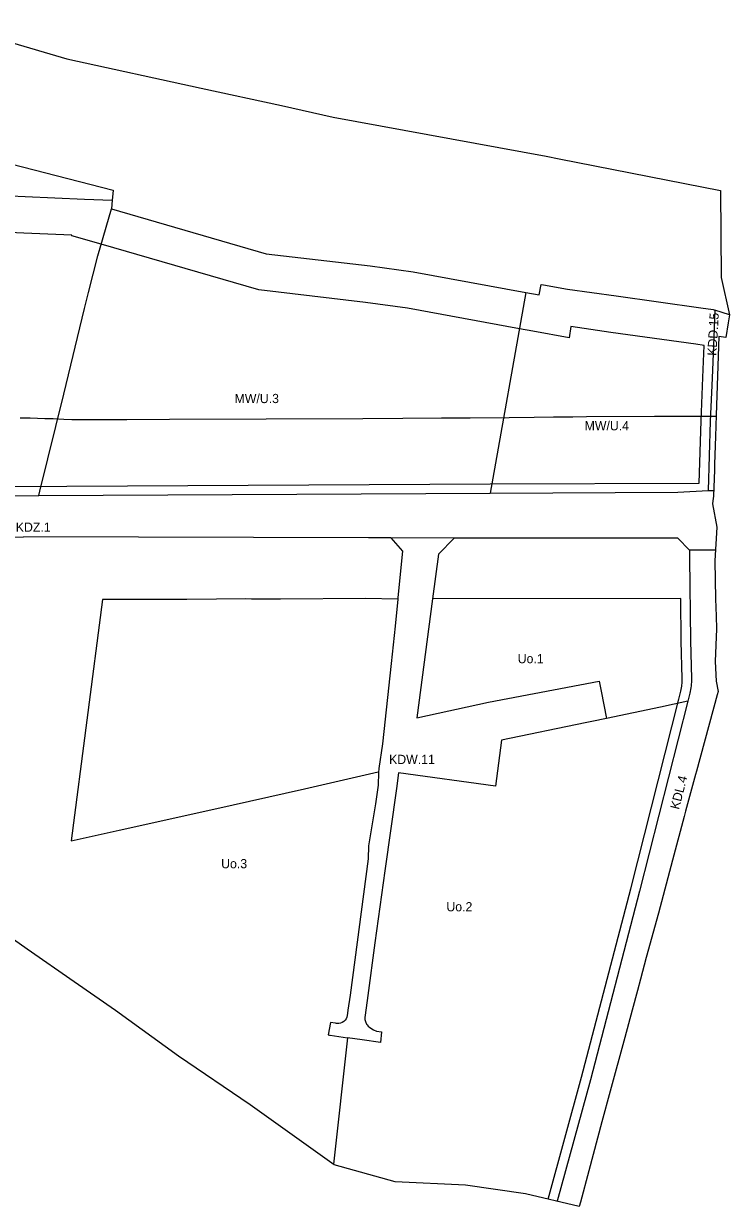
# Model space of a CAD drawing. Extents: x 7416797 to 7419013, y 5549660 to 5551534.
# Drawn here: x 7418629 to 7419013, y 5549660 to 5550303 of the extents above; entities that cross this region are included whole.
import ezdxf

# ---------------------------------------------------------------- set-up
doc = ezdxf.new("R2010")
doc.units = 0
for name, color, linetype in [('LIN_Linia Zabudowy Nieprzekraczalna', 7, 'Continuous'), ('LIN_linie_rozgraniczajace', 7, 'Continuous'), ('LIN_nieprzekraczalna_linia_regulacyjna', 7, 'Continuous'), ('TXT_Oznaczenia_przeznaczen', 7, 'Continuous')]:
    doc.layers.add(name, color=color, linetype=linetype)

msp = doc.modelspace()

# ---------------------------------------------------------------- linework, layer by layer
at = {"layer": 'LIN_Linia Zabudowy Nieprzekraczalna'}
for points in [[(7418999, 5550127.95), (7418994.39, 5550128.59), (7418948.33, 5550135.03), (7418926.58, 5550138.15), (7418925.52, 5550132.14), (7418905.84, 5550135.72), (7418898.57, 5550137.05), (7418837.64, 5550148.14), (7418814.89, 5550151.38), (7418756.87, 5550158.17), (7418671.17, 5550182.99), (7418655.19, 5550187.61), (7418655.21, 5550187.83), (7418629.07, 5550188.98), (7418613.18, 5550189.67)], [(7418553.78, 5550050.88), (7418882.6, 5550052.65), (7418996.26, 5550053.11), (7418997.29, 5550086.86), (7418998.27, 5550110.48), (7418999, 5550127.95)], [(7418832.42, 5549989.99), (7418814.81, 5549990.28), (7418768.7, 5549989.97), (7418757.85, 5549989.93), (7418752.89, 5549989.99), (7418749.61, 5549990.03), (7418733.84, 5549989.93), (7418717.77, 5549989.82), (7418707.07, 5549989.76), (7418671.86, 5549989.69), (7418654.93, 5549858.47), (7418680.95, 5549864.34), (7418732.43, 5549875.79), (7418781.66, 5549886.84), (7418821.77, 5549896.04), (7418822, 5549896.07)], [(7418987.05, 5549945.7), (7418987.02, 5549946.7), (7418986.49, 5549967.05), (7418986.24, 5549990.28), (7418851.28, 5549990.03)], [(7418914.18, 5549663.67), (7418932.35, 5549729.88), (7418959.07, 5549832.37), (7418985.19, 5549935.46), (7418986.31, 5549939.88), (7418986.81, 5549942.59)]]:
    msp.add_lwpolyline(points, dxfattribs=at)
msp.add_arc((7418972.06, 5549945.31), 15, 349.53236, 1.50593, dxfattribs=at)
at = {"layer": 'LIN_linie_rozgraniczajace'}
for p, q in [((7418677.18, 5550206.89), (7418676.72, 5550202.2)), ((7418637.27, 5550046.33), (7418882.7, 5550047.65)), ((7419005.09, 5550016.52), (7418991.01, 5550016.57)), ((7418805.17, 5549751.39), (7418797.44, 5549682.56))]:
    msp.add_line(p, q, dxfattribs=at)
for points in [[(7418587.07, 5550302.96), (7418652.56, 5550283.78), (7418725.47, 5550267.96), (7418769.21, 5550258.51), (7418797.38, 5550252.01), (7418913.17, 5550230.8), (7418920.15, 5550229.52), (7419007.9, 5550212.21), (7419008.26, 5550164.94), (7419012.67, 5550144.66), (7419011.97, 5550140.29), (7419010.7, 5550132.33), (7419006.93, 5550132.81), (7419005.43, 5550089.99), (7419005.2, 5550078.33), (7419004.68, 5550063.45), (7419004.56, 5550060.35), (7419004.05, 5550046.02), (7419003.78, 5550043.42), (7419003.6, 5550041.8), (7419005.92, 5550029.08), (7419004.71, 5550010.77), (7419005.11, 5549990.11), (7419005.45, 5549980.75), (7419005.71, 5549973.72), (7419005.04, 5549956), (7419005.52, 5549945.28), (7419006.63, 5549939.77), (7419006.01, 5549937.92), (7418994.75, 5549896.44), (7418994.23, 5549894.5), (7418988.87, 5549874.66), (7418988.08, 5549871.69), (7418981.78, 5549848.06), (7418974.08, 5549819.09), (7418967.49, 5549795.05), (7418964.31, 5549783.19), (7418962.66, 5549777.04), (7418959.8, 5549766.43), (7418955.79, 5549751.47), (7418947.91, 5549722.35), (7418943.38, 5549705.58), (7418936.28, 5549679.04), (7418931.71, 5549661.99), (7418931.09, 5549659.68), (7418901.92, 5549666.57), (7418869.17, 5549671.11), (7418830.93, 5549673.02), (7418797.76, 5549682.33), (7418752.1, 5549714.85), (7418713.25, 5549741.4), (7418678.9, 5549766.22), (7418656.58, 5549781.83), (7418631, 5549799.52), (7418604.21, 5549818.33)], [(7418517.12, 5550255.55), (7418525.82, 5550252.15), (7418525.02, 5550248.2), (7418548.28, 5550242.6), (7418549.21, 5550245.86), (7418585.2, 5550236.1), (7418677.71, 5550212.39), (7418677.52, 5550210.42), (7418677.18, 5550206.89)], [(7418580.75, 5550210.9), (7418598.18, 5550210.35), (7418614.05, 5550209.65), (7418629.94, 5550208.96), (7418662.13, 5550207.55), (7418677.18, 5550206.89)], [(7418637.27, 5550046.33), (7418637.87, 5550048.73), (7418650.92, 5550101.52), (7418662.1, 5550147.99), (7418664.31, 5550156.81), (7418669.36, 5550176.73), (7418676.72, 5550202.2)], [(7418676.72, 5550202.2), (7418760.84, 5550177.84), (7418817.46, 5550171.22), (7418840.84, 5550167.89), (7418902.07, 5550156.74)], [(7418902.07, 5550156.74), (7418882.7, 5550047.65)], [(7418902.07, 5550156.74), (7418909.3, 5550155.42), (7418910.3, 5550161.12), (7418911.7, 5550160.88), (7418924.7, 5550158.63), (7418951.14, 5550154.83), (7418997.16, 5550148.4), (7419003.89, 5550147.46), (7419004.81, 5550147.17)], [(7419004.81, 5550147.17), (7419004.2, 5550132.51), (7419003.26, 5550110.14), (7419002.28, 5550086.71), (7419001.14, 5550048.97)], [(7419012.67, 5550144.66), (7419004.81, 5550147.17)], [(7418536.01, 5550045.66), (7418553.84, 5550045.88), (7418637.27, 5550046.33)], [(7418882.7, 5550047.65), (7418984.73, 5550048.06), (7419001.14, 5550048.97)], [(7419001.14, 5550048.97), (7419004.16, 5550049.02)], [(7418603.02, 5550023.61), (7418629.04, 5550023.75)], [(7418828.71, 5550023.21), (7418816.46, 5550023.24), (7418629.04, 5550023.75)], [(7418828.71, 5550023.21), (7418835.02, 5550016.03), (7418832.51, 5549990.88), (7418832.42, 5549989.99), (7418830.95, 5549975.21), (7418828.81, 5549954.94), (7418824.15, 5549911.23), (7418822.05, 5549897.85), (7418821.99, 5549895.73), (7418821.78, 5549888.8), (7418820.4, 5549878.62), (7418816.53, 5549855.85), (7418816.24, 5549848.72), (7418806.49, 5549774.55), (7418805.3, 5549766.47)], [(7418863.08, 5550023.15), (7418828.71, 5550023.21)], [(7418863.08, 5550023.15), (7418854.48, 5550014.44), (7418851.28, 5549990.03), (7418842.79, 5549925.4), (7418881.75, 5549933.93), (7418941.87, 5549945.39), (7418942.96, 5549939.91), (7418945.97, 5549925.1)], [(7418991.01, 5550016.57), (7418984.73, 5550023.14), (7418922.75, 5550023.04), (7418863.08, 5550023.15)], [(7418991.01, 5550016.57), (7418991.01, 5550012.23), (7418991.49, 5549967.18), (7418992.02, 5549946.83), (7418992.05, 5549945.84)], [(7418992.05, 5549945.84), (7418992.05, 5549944.79), (7418991.99, 5549943.75), (7418991.89, 5549942.71), (7418991.72, 5549941.68)], [(7418991.72, 5549941.68), (7418991.19, 5549938.81), (7418990.09, 5549934.47)], [(7418990.09, 5549934.47), (7418963.91, 5549831.13), (7418937.18, 5549728.58), (7418919.05, 5549662.52)], [(7418990.09, 5549934.47), (7418975.22, 5549931.25), (7418945.97, 5549925.1)], [(7418945.97, 5549925.1), (7418937.98, 5549923.42), (7418934.26, 5549922.66), (7418888.82, 5549913.19), (7418885.48, 5549888.29), (7418832.9, 5549895.45), (7418831.67, 5549886.95), (7418825.31, 5549842.17), (7418820.04, 5549803.06), (7418816.12, 5549774.42), (7418814.78, 5549763.72), (7418814.6, 5549762.32)], [(7418805.3, 5549766.47), (7418805.26, 5549766.16), (7418804.85, 5549763.41), (7418804.65, 5549762.56), (7418804.28, 5549761.72), (7418803.74, 5549760.93), (7418803.05, 5549760.25), (7418802.24, 5549759.71), (7418801.36, 5549759.35), (7418800.46, 5549759.17), (7418799.59, 5549759.14), (7418799.16, 5549759.19), (7418799.11, 5549759.2), (7418798.6, 5549759.28)], [(7418798.6, 5549759.28), (7418795.87, 5549759.72), (7418794.56, 5549752.96), (7418794.79, 5549752.92), (7418795.28, 5549752.85), (7418795.62, 5549752.8), (7418805.17, 5549751.39)], [(7418815.87, 5549758.33), (7418816.32, 5549757.71), (7418817.16, 5549756.91), (7418819.29, 5549755.65), (7418820.9, 5549755.02), (7418823.57, 5549754.55), (7418822.98, 5549748.77), (7418813.09, 5549750.23), (7418805.17, 5549751.39)], [(7418814.6, 5549762.32), (7418814.57, 5549761.8), (7418814.58, 5549761.28), (7418814.66, 5549760.75), (7418814.79, 5549760.23), (7418814.97, 5549759.73), (7418815.2, 5549759.25), (7418815.49, 5549758.81), (7418815.81, 5549758.4), (7418815.87, 5549758.33)]]:
    msp.add_lwpolyline(points, dxfattribs=at)
at = {"layer": 'LIN_nieprzekraczalna_linia_regulacyjna'}
msp.add_lwpolyline([(7419005.42, 5550089.3), (7418977.69, 5550089.3), (7418972.02, 5550089.3), (7418934.96, 5550089.03), (7418927.57, 5550088.96), (7418917.03, 5550088.86), (7418906.48, 5550088.72), (7418893.03, 5550088.53), (7418871.84, 5550088.37), (7418859.01, 5550088.33), (7418856.23, 5550088.33), (7418835.12, 5550088.18), (7418813.38, 5550088.07), (7418708.27, 5550087.58), (7418685.22, 5550087.43), (7418668.29, 5550087.43), (7418665.94, 5550087.44), (7418658.7, 5550087.48), (7418655.16, 5550087.55), (7418650.83, 5550087.7), (7418645.02, 5550087.93), (7418640.59, 5550088.1), (7418632.63, 5550088.3), (7418627.15, 5550088.37)], dxfattribs=at)

# ---------------------------------------------------------------- texts
at = {"layer": 'TXT_Oznaczenia_przeznaczen'}
for s, rotation, p in [('KDD.15', 86.63644, (7419005.63, 5550122.2)), ('KDL.4', 75.68952, (7418985.31, 5549875.21))]:
    msp.add_text(s, height=5, rotation=rotation, dxfattribs=at).set_placement(p)
for s, p in [('MW/U.3', (7418743.7, 5550096.58)), ('MW/U.4', (7418934, 5550081.76)), ('KDZ.1', (7418624.77, 5550026.59)), ('Uo.1', (7418897.63, 5549955.09)), ('KDW.11', (7418827.69, 5549900.29)), ('Uo.3', (7418736.4, 5549843.57)), ('Uo.2', (7418858.85, 5549820.15))]:
    msp.add_text(s, height=5, dxfattribs=at).set_placement(p)

doc.saveas('drawing.dxf')
